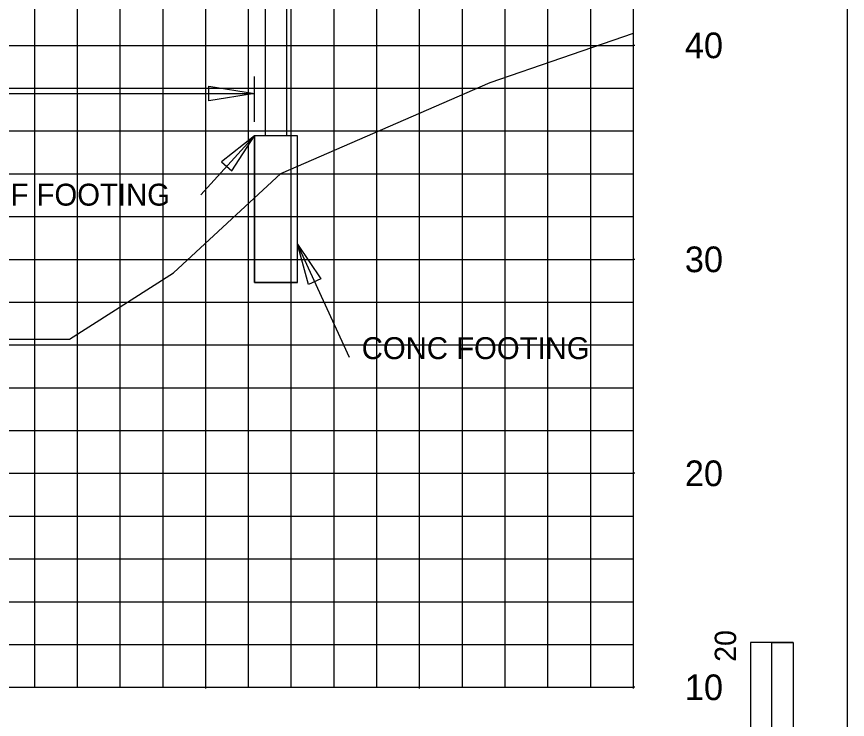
# Model space of a CAD drawing. Extents: x 1797809 to 2198143, y 249608 to 1237864.
# Drawn here: x 2194648.84 to 2194687.69, y 1237161.61 to 1237194.45 of the extents above; entities that cross this region are included whole.
import ezdxf

# ---------------------------------------------------------------- set-up
doc = ezdxf.new("R2010")
doc.units = 0
for name, color, linetype in [('29', 7, 'Continuous'), ('3', 7, 'Continuous'), ('31', 7, 'Continuous'), ('60', 7, 'Continuous'), ('DESIGN - SHEET - Light Grid', 7, 'Continuous'), ('GSDIMS', 7, 'Continuous'), ('GSSHT', 7, 'Continuous'), ('Level 55', 7, 'Continuous'), ('Level 61', 7, 'Continuous'), ('V7Level1', 7, 'Continuous')]:
    doc.layers.add(name, color=color, linetype=linetype)

msp = doc.modelspace()

# ---------------------------------------------------------------- linework, layer by layer
at = {"layer": '29'}
for p, q in [((2194683.16, 1237165.195), (2194683.16, 1237135.195)), ((2194685.16, 1237165.195), (2194683.16, 1237165.195)), ((2194683.16, 1237165.195), (2194683.16, 1237135.195)), ((2194685.16, 1237165.195), (2194683.16, 1237165.195)), ((2194685.16, 1237165.195), (2194685.16, 1237155.195)), ((2194685.16, 1237165.195), (2194685.16, 1237135.195)), ((2194685.16, 1237165.195), (2194685.16, 1237155.195)), ((2194685.16, 1237165.195), (2194685.16, 1237135.195))]:
    msp.add_line(p, q, dxfattribs=at)
msp.add_lwpolyline([(2194684.16, 1237155.195), (2194684.16, 1237165.195), (2194685.16, 1237165.195), (2194685.16, 1237155.195)], close=True, dxfattribs=at)
msp.add_lwpolyline([(2194684.16, 1237155.195), (2194684.16, 1237165.195), (2194685.16, 1237165.195), (2194685.16, 1237155.195)], close=True, dxfattribs=at)
at = {"layer": '3'}
for p, q in [((2194687.688, 1237133.046), (2194687.688, 1237228.046)), ((2194660.459, 1237205.876), (2194660.459, 1237188.876)), ((2194661.459, 1237205.876), (2194661.459, 1237188.876)), ((2194659.959, 1237189.536), (2194659.959, 1237191.651)), ((2194657.457, 1237186.126), (2194659.959, 1237188.876)), ((2194659.959, 1237182.024), (2194659.959, 1237188.876)), ((2194661.983, 1237188.876), (2194659.959, 1237188.876)), ((2194661.983, 1237182.024), (2194661.983, 1237188.876)), ((2194664.409, 1237178.513), (2194661.983, 1237183.815)), ((2194661.983, 1237182.024), (2194659.959, 1237182.024))]:
    msp.add_line(p, q, dxfattribs=at)
at = {"layer": '60'}
for p, q in [((2194677.688, 1237163.106), (2194677.688, 1237223.106)), ((2194677.748, 1237193.106), (2194677.688, 1237193.106)), ((2194677.748, 1237183.106), (2194677.688, 1237183.106)), ((2194677.748, 1237173.106), (2194677.688, 1237173.106)), ((2194547.688, 1237163.106), (2194677.688, 1237163.106)), ((2194657.688, 1237163.046), (2194657.688, 1237163.106)), ((2194667.688, 1237163.046), (2194667.688, 1237163.106)), ((2194677.688, 1237163.046), (2194677.688, 1237163.106)), ((2194677.748, 1237163.106), (2194677.688, 1237163.106))]:
    msp.add_line(p, q, dxfattribs=at)
at = {"layer": 'DESIGN - SHEET - Light Grid'}
msp.add_lwpolyline([(2194648.466, 1237179.379), (2194651.323, 1237179.379), (2194656.174, 1237182.475), (2194661.193, 1237187.111), (2194670.991, 1237191.365), (2194677.688, 1237193.671)], dxfattribs=at)
at = {"layer": 'GSDIMS'}
for points in [[(2194659.959, 1237190.859), (2194657.83, 1237190.511), (2194657.83, 1237191.206)], [(2194659.959, 1237188.876), (2194658.429, 1237187.67), (2194658.903, 1237187.239)], [(2194661.983, 1237183.815), (2194663.075, 1237182.201), (2194662.492, 1237181.934)]]:
    msp.add_lwpolyline(points, close=True, dxfattribs=at)
at = {"layer": 'GSSHT'}
for p, q in [((2194649.688, 1237163.106), (2194649.688, 1237223.106)), ((2194651.688, 1237163.106), (2194651.688, 1237223.106)), ((2194653.688, 1237163.106), (2194653.688, 1237223.106)), ((2194655.688, 1237163.106), (2194655.688, 1237223.106)), ((2194657.688, 1237163.106), (2194657.688, 1237223.106)), ((2194659.688, 1237163.106), (2194659.688, 1237223.106)), ((2194661.688, 1237163.106), (2194661.688, 1237223.106)), ((2194663.688, 1237163.106), (2194663.688, 1237223.106)), ((2194665.688, 1237163.106), (2194665.688, 1237223.106)), ((2194667.688, 1237163.106), (2194667.688, 1237223.106)), ((2194669.688, 1237163.106), (2194669.688, 1237223.106)), ((2194671.688, 1237163.106), (2194671.688, 1237223.106)), ((2194673.688, 1237163.106), (2194673.688, 1237223.106)), ((2194675.688, 1237163.106), (2194675.688, 1237223.106)), ((2194677.688, 1237163.106), (2194677.688, 1237223.106)), ((2194547.688, 1237193.106), (2194677.688, 1237193.106)), ((2194547.688, 1237191.106), (2194677.688, 1237191.106)), ((2194547.688, 1237189.106), (2194677.688, 1237189.106)), ((2194547.688, 1237187.106), (2194677.688, 1237187.106)), ((2194547.688, 1237185.106), (2194677.688, 1237185.106)), ((2194547.688, 1237183.106), (2194677.688, 1237183.106)), ((2194547.688, 1237181.106), (2194677.688, 1237181.106)), ((2194547.688, 1237179.106), (2194677.688, 1237179.106)), ((2194547.688, 1237177.106), (2194677.688, 1237177.106)), ((2194547.688, 1237175.106), (2194677.688, 1237175.106)), ((2194547.688, 1237173.106), (2194677.688, 1237173.106)), ((2194547.688, 1237171.106), (2194677.688, 1237171.106)), ((2194547.688, 1237169.106), (2194677.688, 1237169.106)), ((2194547.688, 1237167.106), (2194677.688, 1237167.106)), ((2194547.688, 1237165.106), (2194677.688, 1237165.106)), ((2194547.688, 1237163.106), (2194677.688, 1237163.106))]:
    msp.add_line(p, q, dxfattribs=at)
at = {"layer": 'Level 61'}
msp.add_line((2194619.959, 1237190.859), (2194659.959, 1237190.859), dxfattribs=at)
at = {"layer": 'V7Level1'}
msp.add_lwpolyline([(2194659.959, 1237182.024), (2194661.983, 1237182.024), (2194661.983, 1237188.876), (2194659.959, 1237188.876)], close=True, dxfattribs=at)

# ---------------------------------------------------------------- texts
at = {"layer": '29'}
msp.add_text('20', height=0.9991, rotation=90.0572, dxfattribs=at).set_placement((2194682.485, 1237164.295))
msp.add_text('20', height=0.9991, rotation=90.0572, dxfattribs=at).set_placement((2194682.485, 1237164.295))
at = {"layer": '31'}
for s, p in [('40', (2194680.088, 1237192.506)), ('30', (2194680.088, 1237182.506)), ('20', (2194680.088, 1237172.506)), ('10', (2194680.088, 1237162.506))]:
    msp.add_text(s, height=1.2, dxfattribs=at).set_placement(p)
at = {"layer": 'Level 55'}
for s, p in [('EDGE OF FOOTING', (2194643.227, 1237185.616)), ('CONC FOOTING', (2194664.979, 1237178.443))]:
    msp.add_text(s, height=1.02464, dxfattribs=at).set_placement(p)

doc.saveas('drawing.dxf')
